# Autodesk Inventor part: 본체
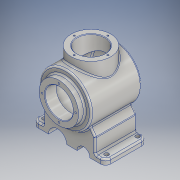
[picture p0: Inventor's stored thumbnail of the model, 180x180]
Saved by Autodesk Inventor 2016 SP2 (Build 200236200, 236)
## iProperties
Created: 2018-08
Part Number: 본체
Material: 알루미늄 6061
Document SubType Name: Modeling
Designer: Administrator
Density: 2.7 g/cm^3
Appearance: 알루미늄 - 평지
Mass: 1879.09 g
Surface Area: 1087.45 cm^2
Volume: 695.959 cm^3
Author: Administrator
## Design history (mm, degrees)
sketch "스케치1"
  geometry: L1 (12, 132)-(108.671, 132); L2 (120, 82)-(0, 82); L3 (0, 82)-(0, 120); L4 (12, 132)-(12, 120); L5 (12, 120)-(0, 120); L6 (102.163, 122)-(22, 122); L7 (22, 122)-(22, 109); L8 (0, 109)-(22, 109); L9 (0, 82)-(0, 109); A1 r 116 centre (4, 82) between (120, 82) and (108.671, 132); A2 r 106 centre (4, 82) between (110, 82) and (102.163, 122); 1 further point
  constraints: 18 end point, 4 point on circle, 4 point on line, 3 vertical, 2 centre point, 2 horizontal, 1 parallel
  dimensions: "d0" = 82 distance from line of point (0, 0) L2; "d2" = 12 distance of L4.end L3.end; "d4" = 76 diameter of L5 L2; "d5" = 100 diameter of L1 L2; "d6" = 116 radius of A1; "d7" = 120 distance from line of L3 L2.start; "d8" = 10 radial gap between concentric circles of A1 A2; "d9" = 22 distance of L8.start L7.end; "d10" = 54 diameter of L8 L2; "d11" = 10 distance between parallel lines of L1 L6; "d131" = 108 distance from line of L2.start L4 (derived)
revolve "회전1" stored, may be unused: angle "d12" = 90 deg
sketch "스케치2"
  geometry: L1 (0, 0)-(32, 0); L2 (0, -70)-(0, 0); L3 (10, -70)-(10, -50); L4 (10, -50)-(38.563, -50); L5 (10, -70)-(0, -70); L6 (38.563, -50)-(52.41, -40.304); L7 (0, 70)-(0, 0); L8 (10, 70)-(10, 50); L9 (10, 50)-(38.563, 50); L10 (10, 70)-(0, 70); L11 (38.563, 50)-(52.41, 40.304); A1 r 50 centre (82, 0) between (32, 0) and (52.41, -40.304) reference
  constraints: 22 end point, 5 symmetric about line, 2 horizontal, 2 point on circle, 1 perpendicular, 1 vertical
  dimensions: "d13" = 82 distance from line of L2 A1.centre; "d14" = 70 distance of L2.start L1.start; "d15" = 10 distance of L3.start L2.start; "d16" = 20 distance of L3.start L3.end; "d19" = 35 deg angle of L5 L6
node "작업 평면1"
sketch "스케치3"
  geometry: L1 (0, -82)-(-70, -82); L2 (-70, -82)-(-70, -72); L3 (-70, -72)-(-50, -72); L4 (-50, -72)-(-50, -43.437); L5 (0, -82)-(0, -50); L6 (-70, -72)-(-40.304, -29.59); L7 (0, -82)-(70, -82); L8 (70, -82)-(70, -72); L9 (70, -72)-(50, -72); L10 (50, -72)-(50, -43.437); L11 (70, -72)-(40.304, -29.59); A1 r 50 centre (0, 0) between (0, -50) and (-40.304, -29.59) reference
  constraints: 22 end point, 5 symmetric about line, 3 perpendicular, 2 point on circle, 2 point on line, 1 horizontal, 1 vertical
  dimensions: "d21" = 70 distance of L1.start L1.end; "d22" = 10 distance of L1.end L2.end; "d23" = 35 deg angle of L2 L6; "d24" = 20 distance of L2.end L3.end
extrude "돌출1" join sketch "스케치3" stored distance "d25" = 80; taper "d26" = 0 deg
revolve "회전2" stored, may be unused: angle "d27" = 90 deg
sketch "스케치4"
  geometry: L1 (-70, -82)-(70, -82) reference; C1 r 17.5 at (-22.5, -82); C2 r 12.5 at (27.5, -82); 1 further point
  constraints: 2 centre point, 2 point on line
  dimensions: "d28" = 35 diameter of C1; "d29" = 22.5 distance of point (0, -82) C1.centre; "d30" = 25 diameter of C2; "d31" = 27.5 distance of point (0, -82) C2.centre
extrude "돌출2" cut sketch "스케치4" distance "d32" = 140; taper "d33" = 0 deg
node "작업 평면2"
sketch "스케치6"
  geometry: L1 (-22, 5)-(112.534, 5); L2 (-22, -33)-(-22, 43) reference; C1 r 38 at (40, 5)
  constraints: 2 end point, 1 centre point, 1 horizontal, 1 point on line
  dimensions: "d35" = 76 diameter of C1; "d36" = 62 distance from line of L2 C1.centre
extrude "돌출3" join sketch "스케치6" stored distance "d37" = 140; taper "d38" = 0 deg
hole "구멍1" diameter "d41" = 54; stored, may be unused: countersink angle "d45" = 90 deg, drill point angle "d47" = 118 deg; dims "d39" = 10, "d40" = 10, "d42" = 6, "d43" = 4, "d44" = 2, "d46" = 8
sketch "스케치7" dims "d48" = 65
  geometry: L1 (0, 0)-(0, 32.5); C1 r 38 at (0, 0) reference; C2 r 3.693 at (0, 32.5); C3 r 3.693 at (-32.5, 0); C4 r 3.693 at (0, -32.5); C5 r 3.693 at (32.5, 0); 1 further point
  constraints: 4 centre point, 2 coincident, 2 end point, 1 vertical, 1 vertical alignment, 11 other
  dimensions: "d51" = 360 deg dimension on C1.centre C2.centre (derived)
sketch "스케치8" dims "d53" = 65
  geometry: L1 (0, 0)-(0, 32.5); C1 r 38 at (0, 0) reference; C2 r 4.049 at (0, 32.5); C3 r 4.049 at (-32.5, 0); C4 r 4.049 at (0, -32.5); C5 r 4.049 at (32.5, 0); 1 further point
  constraints: 4 centre point, 2 coincident, 2 end point, 1 vertical, 1 vertical alignment, 11 other
  dimensions: "d56" = 360 deg dimension on C1.centre C2.centre (derived)
hole "구멍2" sketch "스케치8" at (-32.5, 0), (0, 32.5), (32.5, 0), (0, -32.5) diameter "d58" = 3.242; stored, may be unused: countersink angle "d62" = 90 deg, drill point angle "d64" = 118 deg; dims "d59" = 8, "d60" = 4, "d61" = 2, "d63" = 10
hole "구멍3" sketch "스케치7" diameter "d65" = 3.242; stored, may be unused: countersink angle "d69" = 90 deg, drill point angle "d71" = 118 deg; dims "d66" = 8, "d67" = 4, "d68" = 2, "d70" = 10
fillet "모깎기1" dims "d72" = 3
fillet "모깎기2" dims "d73" = 3
fillet "모깎기3" dims "d74" = 10
hole "구멍4" diameter "d77" = 8; stored, may be unused: countersink angle "d81" = 90 deg, drill point angle "d83" = 0 deg; dims "d75" = 10, "d76" = 10, "d78" = 8, "d79" = 4, "d80" = 2, "d82" = 10
hole "구멍5" diameter "d86" = 8; stored, may be unused: countersink angle "d90" = 90 deg, drill point angle "d92" = 0 deg; dims "d84" = 10, "d85" = 10, "d87" = 8, "d88" = 4, "d89" = 2, "d91" = 10
hole "구멍6" diameter "d95" = 8; stored, may be unused: countersink angle "d99" = 90 deg, drill point angle "d101" = 0 deg; dims "d93" = 10, "d94" = 10, "d96" = 8, "d97" = 4, "d98" = 2, "d100" = 10
hole "구멍7" diameter "d104" = 8; stored, may be unused: countersink angle "d108" = 90 deg, drill point angle "d110" = 0 deg; dims "d102" = 10, "d103" = 10, "d105" = 8, "d106" = 4, "d107" = 2, "d109" = 10
fillet "모깎기4" dims "d111" = 3
fillet "모깎기5" dims "d112" = 3
fillet "모깎기6" dims "d113" = 3
fillet "모깎기7" dims "d114" = 3
fillet "모깎기8" dims "d115" = 3
chamfer "모따기1" distance "d116" = 1; stored, may be unused: second distance "d117" = 2, angle "d118" = 45 deg
chamfer "모따기2" distance "d119" = 1; stored, may be unused: second distance "d120" = 2, angle "d121" = 45 deg
node "작업 평면3"
sketch "스케치9"
  geometry: L1 (0, 0)-(0, -66.979); L2 (0, 0)-(0, 47.875); L3 (0, 0)-(32.5, 0); C1 r 50 at (0, 0) reference; A1 r 32.5 centre (0, 0) between (0, -32.5) and (32.5, 0); 1 further point
  constraints: 6 end point, 2 point on circle, 2 vertical, 1 centre point, 1 coincident, 1 point on line, 1 other
  dimensions: "d122" = 65 diameter of A1
feature "엠보싱1" sketch "스케치9" dims "d0" = 82, "d2" = 12, "d4" = 76, "d5" = 100, "d6" = 116, "d7" = 120, "d8" = 10, "d9" = 22, "d10" = 54, "d11" = 10, "d13" = 82, "d14" = 70, "d15" = 10, "d16" = 20, "d19" = 35 deg, "d123" = 0.5, "d124" = 0, "d131" = 108 (derived)
node "직접 편집1"
node "직접 편집2"
node "솔리드1"
mirror "대칭1"
node "투영된 루프1"
feature "이동1" dims "d127" = 2
feature "이동2" dims "d130" = -2
other parameters: "d20" = -62, "d34" = -147, "d125" = 0, "d126" = 0, "d128" = 0, "d129" = 0
